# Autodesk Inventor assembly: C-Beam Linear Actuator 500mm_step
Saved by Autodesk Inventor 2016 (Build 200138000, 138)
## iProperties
Created: 2016-01
Part Number: C-Beam Linear Actuator 500mm_step
Document SubType Name: Assembly
Designer: John
Author: John
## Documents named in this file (19)
- D:\3D Printer Designs\John Ledden Designs\DLP Printer\V2\C-Beam Linear Actuator 500mm_step.iam
- D:\3D Printer Designs\John Ledden Designs\DLP Printer\V2\Low Profile Screw M5_M5 x 25.ipt
- D:\3D Printer Designs\John Ledden Designs\DLP Printer\V2\Flexible Coupling 0.25in x 8mm.ipt
- D:\3D Printer Designs\John Ledden Designs\DLP Printer\V2\C-Beam 40x80x500 Linear Rail.ipt
- D:\3D Printer Designs\John Ledden Designs\DLP Printer\V2\Xtreme Mini V Wheel_Eccentric.iam
- D:\3D Printer Designs\John Ledden Designs\DLP Printer\V2\Nylon Insert Lock Nut M5.ipt
- D:\3D Printer Designs\John Ledden Designs\DLP Printer\V2\Lock Collar 8mm.ipt
- D:\3D Printer Designs\John Ledden Designs\DLP Printer\V2\8mm Acme Nut Block.ipt
- D:\3D Printer Designs\John Ledden Designs\DLP Printer\V2\Low Profile Screw M5_M5 x 20.ipt
- D:\3D Printer Designs\John Ledden Designs\DLP Printer\V2\Ball Bearing 8 x 16 x 5.ipt
- D:\3D Printer Designs\John Ledden Designs\DLP Printer\V2\Nema 23 Stepper Motor.ipt
- D:\3D Printer Designs\John Ledden Designs\DLP Printer\V2\C-Beam End Mount.ipt
- D:\3D Printer Designs\John Ledden Designs\DLP Printer\V2\C-Beam Gantry Plate.ipt
- D:\3D Printer Designs\John Ledden Designs\DLP Printer\V2\Aluminum Spacer 3mm.ipt
- D:\3D Printer Designs\John Ledden Designs\DLP Printer\V2\Aluminum Spacer 40mm.ipt
- D:\3D Printer Designs\John Ledden Designs\DLP Printer\V2\Low Profile Screw M5_M5 x 55.ipt
- D:\3D Printer Designs\John Ledden Designs\DLP Printer\V2\Xtreme Mini V Wheel_Straight.iam
- D:\3D Printer Designs\John Ledden Designs\DLP Printer\V2\Shim Washer 8mm.ipt
- D:\3D Printer Designs\John Ledden Designs\DLP Printer\V2\8mm leadscrew 540mm.ipt
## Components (40 placed, 40 different names)
1. Low Profile Screw M5_M5 x 25_1021
2. Flexible Coupling 0.25in x 8mm_1022
3. C-Beam 40x80x500 Linear Rail_1023
4. Xtreme Mini V Wheel_Eccentric_1024 [sub-assembly]
5. Nylon Insert Lock Nut M5_1025
6. Lock Collar 8mm_1026
7. Low Profile Screw M5_M5 x 25_1027
8. 8mm Acme Nut Block_1028
9. Low Profile Screw M5_M5 x 20_1029
10. Ball Bearing 8 x 16 x 5_1030
11. Low Profile Screw M5_M5 x 20_1031
12. Low Profile Screw M5_M5 x 20_1032
13. Nema 23 Stepper Motor_1033
14. C-Beam End Mount_1034
15. Xtreme Mini V Wheel_Eccentric_1035 [sub-assembly]
16. Low Profile Screw M5_M5 x 20_1036
17. Lock Collar 8mm_1037
18. Low Profile Screw M5_M5 x 25_1038
19. C-Beam Gantry Plate_1039
20. Low Profile Screw M5_M5 x 20_1040
21. Ball Bearing 8 x 16 x 5_1041
22. Aluminum Spacer 3mm_1042
23. Low Profile Screw M5_M5 x 20_1043
24. Low Profile Screw M5_M5 x 20_1044
25. Aluminum Spacer 40mm_1045
26. Low Profile Screw M5_M5 x 55_1046
27. Xtreme Mini V Wheel_Straight_1047 [sub-assembly]
28. Low Profile Screw M5_M5 x 20_1048
29. Shim Washer 8mm_1049
30. Low Profile Screw M5_M5 x 25_1050
31. 8mm leadscrew 540mm_1051
32. C-Beam End Mount_1052
33. Aluminum Spacer 3mm_1053
34. Nylon Insert Lock Nut M5_1054
35. Low Profile Screw M5_M5 x 20_1055
36. Aluminum Spacer 40mm_1056
37. Low Profile Screw M5_M5 x 55_1057
38. Xtreme Mini V Wheel_Straight_1058 [sub-assembly]
39. Low Profile Screw M5_M5 x 20_1059
40. Shim Washer 8mm_1060
